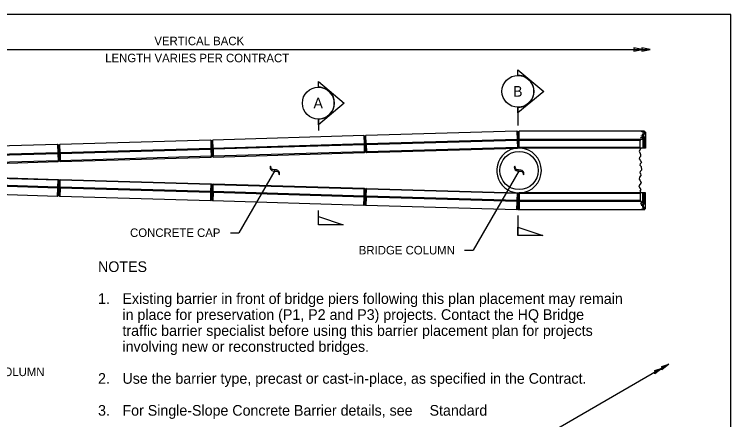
# Model space of a CAD drawing. Extents: x 99862 to 103151, y 100000 to 102076.
# Drawn here: x 101804 to 103151, y 101314 to 102076 of the extents above; entities that cross this region are included whole.
import ezdxf

# ---------------------------------------------------------------- set-up
doc = ezdxf.new("R2010")
doc.units = 0
for name, color, linetype in [('Level 1', 7, 'Continuous'), ('Level 15', 7, 'Continuous'), ('Level 19', 7, 'Continuous'), ('Level 2', 7, 'Continuous'), ('Level 20', 7, 'Continuous'), ('Level 25', 7, 'Continuous'), ('Level 41', 7, 'Continuous'), ('Level 60', 7, 'Continuous'), ('Level 8', 7, 'Continuous'), ('Level 9', 7, 'Continuous')]:
    doc.layers.add(name, color=color, linetype=linetype)

msp = doc.modelspace()

# ---------------------------------------------------------------- linework, layer by layer
at = {"layer": 'Level 1'}
msp.add_lwpolyline([(99862, 99999.5), (103151, 99999.5), (103151, 102075.5), (99862, 102075.5)], close=True, dxfattribs=at)
at = {"layer": 'Level 15'}
for p, q in [((101310.7, 102009.5), (102999.7, 102009.5)), ((102293.6, 101782.2), (102226.1, 101665.2)), ((102753, 101782.1), (102666.6, 101632.4)), ((102210.1, 101665.2), (102226.1, 101665.2)), ((102650.6, 101632.4), (102666.6, 101632.4)), ((103034.9, 101418.4), (101857.3, 100738.4))]:
    msp.add_line(p, q, dxfattribs=at)
for points in [[(102984.7, 102009.5), (102969, 102012.6), (102969.7, 102009.5), (102969, 102006.4)], [(102999.7, 102009.5), (102984, 102012.6), (102984.7, 102009.5), (102984, 102006.4)]]:
    msp.add_lwpolyline(points, close=True, dxfattribs=at)
at = {"layer": 'Level 19'}
for p, q in [((102754.9, 101824.1), (102751.1, 101824.1)), ((102751.1, 101740.2), (102754.9, 101740.2))]:
    msp.add_line(p, q, dxfattribs=at)
msp.add_circle((102753, 101782.1), 36, dxfattribs=at)
for start, end in [(92.5929, 240), (272.5929, 87.4071), (240, 267.4071)]:
    msp.add_arc((102753, 101782.1), 42, start, end, dxfattribs=at)
at = {"layer": 'Level 2'}
for p, q in [((102748.9, 101856.1), (102465, 101847.8)), ((102748.9, 101856.1), (102749.3, 101840.3)), ((102750.4, 101854.6), (102748.9, 101856.1)), ((102750.4, 101854.6), (102750.9, 101838.9)), ((102750.4, 101854.6), (102751.4, 101854.6)), ((102751.4, 101854.6), (102752.9, 101856.1)), ((102751.4, 101838.9), (102751.4, 101854.6)), ((102752.9, 101840.4), (102752.9, 101856.1)), ((102988.8, 101856.1), (102752.9, 101856.1)), ((102982.8, 101855.3), (102988.8, 101856.1)), ((102990.8, 101854.3), (102982.8, 101855.3)), ((102984.9, 101852.8), (102988.1, 101853.5)), ((102988.1, 101853.5), (102990.8, 101854.3)), ((102988.1, 101853.5), (102988.1, 101851.9)), ((102988.8, 101856.1), (102988.8, 101854.6)), ((102990.8, 101854.3), (102990.8, 101851.2)), ((102461, 101847.7), (102177.1, 101839.4)), ((102462.5, 101846.2), (102461, 101847.7)), ((102461, 101847.7), (102461.5, 101832)), ((102463.5, 101846.2), (102462.5, 101846.2)), ((102463, 101830.5), (102462.5, 101846.2)), ((102463.5, 101846.2), (102465, 101847.8)), ((102464, 101830.5), (102463.5, 101846.2)), ((102465.5, 101832.1), (102465, 101847.8)), ((102749.3, 101840.3), (102465.5, 101832.1)), ((102749.3, 101840.3), (102750.1, 101839.5)), ((102750.1, 101839.5), (102749.4, 101838.6)), ((102750.1, 101839.5), (102750.9, 101838.9)), ((102752.2, 101839.5), (102751.4, 101838.9)), ((102752.9, 101840.4), (102752.2, 101839.5)), ((102752.2, 101839.5), (102752.9, 101838.6)), ((102982, 101840.4), (102752.9, 101840.4)), ((102980.5, 101838.6), (102982, 101840.4)), ((102981.7, 101844), (102987, 101845.1)), ((102982.8, 101842.9), (102981.7, 101844)), ((102982, 101840.4), (102986, 101841.1)), ((102982.8, 101847.5), (102987, 101848.2)), ((102983.3, 101846.8), (102982.8, 101847.5)), ((102986, 101842.1), (102982.8, 101842.9)), ((102988.6, 101845.7), (102983.3, 101846.8)), ((102984.4, 101849.6), (102987, 101850.4)), ((102987, 101848.2), (102984.4, 101849.6)), ((102990.8, 101851.2), (102984.9, 101852.8)), ((102986, 101841.1), (102986, 101842.1)), ((102986, 101841.1), (102986, 101824.1)), ((102987, 101850.4), (102990.8, 101851.2)), ((102987, 101850.4), (102987, 101848.2)), ((102987, 101848.2), (102987, 101846)), ((102987, 101845.1), (102988.6, 101845.7)), ((102987, 101845.1), (102987, 101824.1)), ((102988.6, 101845.7), (102988.6, 101824.1)), ((102990.8, 101851.2), (102990.8, 101824.1)), ((101885.2, 101830.9), (101601.4, 101822.6)), ((101886.8, 101829.4), (101885.2, 101830.9)), ((101885.2, 101830.9), (101885.7, 101815.2)), ((101887.8, 101829.4), (101886.8, 101829.4)), ((101887.2, 101813.7), (101886.8, 101829.4)), ((101887.8, 101829.4), (101889.2, 101831)), ((101888.2, 101813.7), (101887.8, 101829.4)), ((102173.1, 101839.3), (101889.2, 101831)), ((101889.7, 101815.3), (101889.2, 101831)), ((102174.7, 101837.8), (102173.1, 101839.3)), ((102173.1, 101839.3), (102173.6, 101823.6)), ((102175.7, 101837.8), (102174.7, 101837.8)), ((102175.1, 101822.1), (102174.7, 101837.8)), ((102175.7, 101837.8), (102177.1, 101839.4)), ((102176.1, 101822.1), (102175.7, 101837.8)), ((102177.6, 101823.7), (102177.1, 101839.4)), ((102461.5, 101832), (102177.6, 101823.7)), ((102461.5, 101830.2), (102177.6, 101821.9)), ((102461.5, 101832), (102462.2, 101831.1)), ((102462.2, 101831.1), (102461.5, 101830.2)), ((102461.5, 101830.2), (102461.9, 101817.2)), ((102462.2, 101831.1), (102463, 101830.5)), ((102464, 101830.5), (102463, 101830.5)), ((102463.4, 101817.2), (102463, 101830.5)), ((102464.7, 101831.2), (102464, 101830.5)), ((102464.4, 101817.3), (102464, 101830.5)), ((102465.5, 101832.1), (102464.7, 101831.2)), ((102464.7, 101831.2), (102465.5, 101830.3)), ((102749.4, 101838.6), (102465.5, 101830.3)), ((102465.5, 101830.3), (102465.9, 101817.3)), ((102749.4, 101838.6), (102749.8, 101825.6)), ((102751.3, 101825.6), (102750.9, 101838.9)), ((102751.4, 101825.6), (102751.4, 101838.9)), ((102752.9, 101825.6), (102752.9, 101838.6)), ((102980.5, 101838.6), (102752.9, 101838.6)), ((102980.5, 101825.6), (102980.5, 101838.6)), ((101885.7, 101815.2), (101601.8, 101806.9)), ((101885.7, 101813.4), (101601.9, 101805.1)), ((101885.7, 101815.2), (101886.5, 101814.3)), ((101886.5, 101814.3), (101885.7, 101813.4)), ((101885.7, 101813.4), (101886.1, 101800.4)), ((101886.5, 101814.3), (101887.2, 101813.7)), ((101888.2, 101813.7), (101887.2, 101813.7)), ((101887.6, 101800.4), (101887.2, 101813.7)), ((101889, 101814.4), (101888.2, 101813.7)), ((101888.6, 101800.5), (101888.2, 101813.7)), ((101889.7, 101815.3), (101889, 101814.4)), ((101889, 101814.4), (101889.7, 101813.5)), ((102173.6, 101823.6), (101889.7, 101815.3)), ((102173.6, 101821.8), (101889.7, 101813.5)), ((101889.7, 101813.5), (101890.1, 101800.5)), ((102173.6, 101823.6), (102174.3, 101822.7)), ((102174.3, 101822.7), (102173.6, 101821.8)), ((102173.6, 101821.8), (102174, 101808.8)), ((102174.3, 101822.7), (102175.1, 101822.1)), ((102176.1, 101822.1), (102175.1, 101822.1)), ((102175.5, 101808.8), (102175.1, 101822.1)), ((102176.9, 101822.8), (102176.1, 101822.1)), ((102176.5, 101808.9), (102176.1, 101822.1)), ((102177.6, 101823.7), (102176.9, 101822.8)), ((102176.9, 101822.8), (102177.6, 101821.9)), ((102177.6, 101821.9), (102178, 101808.9)), ((102461.9, 101817.2), (102178, 101808.9)), ((102178, 101807.4), (102461.9, 101815.7)), ((102461.9, 101815.7), (102463.4, 101817.2)), ((102462.7, 101816.5), (102461.9, 101817.2)), ((102462.7, 101816.5), (102461.9, 101815.7)), ((102463.4, 101817.2), (102462.7, 101816.5)), ((102463.4, 101817.2), (102464.4, 101817.3)), ((102464.4, 101817.3), (102465.9, 101815.8)), ((102464.4, 101817.3), (102465.2, 101816.5)), ((102465.2, 101816.5), (102465.9, 101817.3)), ((102465.9, 101815.8), (102465.2, 101816.5)), ((102749.8, 101825.6), (102465.9, 101817.3)), ((102465.9, 101815.8), (102749.8, 101824.1)), ((102750.5, 101824.8), (102749.8, 101825.6)), ((102750.5, 101824.8), (102749.8, 101824.1)), ((102751.3, 101825.6), (102750.5, 101824.8)), ((102752.9, 101824.1), (102751.4, 101825.6)), ((102752.2, 101824.9), (102752.9, 101825.6)), ((102980.5, 101825.6), (102752.9, 101825.6)), ((102990.8, 101824.1), (102752.9, 101824.1)), ((102982, 101824.1), (102980.5, 101825.6)), ((101886.1, 101800.4), (101602.2, 101792.1)), ((101886.9, 101799.7), (101886.1, 101800.4)), ((101886.2, 101798.9), (101887.6, 101800.4)), ((101886.9, 101799.7), (101886.2, 101798.9)), ((101887.6, 101800.4), (101886.9, 101799.7)), ((101887.6, 101800.4), (101888.6, 101800.5)), ((101888.6, 101800.5), (101890.2, 101799)), ((101888.6, 101800.5), (101889.4, 101799.7)), ((101889.4, 101799.7), (101890.1, 101800.5)), ((101890.2, 101799), (101889.4, 101799.7)), ((102174, 101808.8), (101890.1, 101800.5)), ((101890.2, 101799), (102174, 101807.3)), ((102174, 101807.3), (102175.5, 101808.8)), ((102174.8, 101808.1), (102174, 101808.8)), ((102174.8, 101808.1), (102174, 101807.3)), ((102175.5, 101808.8), (102174.8, 101808.1)), ((102175.5, 101808.8), (102176.5, 101808.9)), ((102176.5, 101808.9), (102178, 101807.4)), ((102176.5, 101808.9), (102177.3, 101808.1)), ((102177.3, 101808.1), (102178, 101808.9)), ((102178, 101807.4), (102177.3, 101808.1)), ((101602.3, 101790.6), (101886.2, 101798.9)), ((101886.1, 101763.9), (101602.2, 101772.2)), ((101602.3, 101773.7), (101886.2, 101765.4)), ((101885.7, 101750.9), (101601.9, 101759.2)), ((101885.7, 101750.9), (101886.1, 101763.9)), ((101886.9, 101764.6), (101886.1, 101763.9)), ((101887.6, 101763.9), (101886.2, 101765.4)), ((101886.9, 101764.6), (101886.2, 101765.4)), ((101887.6, 101763.9), (101886.9, 101764.6)), ((101887.6, 101763.9), (101887.2, 101750.6)), ((101887.6, 101763.9), (101888.6, 101763.8)), ((101888.6, 101763.8), (101888.2, 101750.6)), ((101890.2, 101765.3), (101888.6, 101763.8)), ((101888.6, 101763.8), (101889.4, 101764.6)), ((101890.2, 101765.3), (101889.4, 101764.6)), ((101889.4, 101764.6), (101890.1, 101763.8)), ((101889.7, 101750.8), (101890.1, 101763.8)), ((102174, 101755.5), (101890.1, 101763.8)), ((101890.2, 101765.3), (102174, 101757)), ((101885.7, 101749.1), (101601.8, 101757.4)), ((101885.2, 101733.4), (101885.7, 101749.1)), ((101886.5, 101750), (101885.7, 101750.9)), ((101885.7, 101749.1), (101886.5, 101750)), ((101886.5, 101750), (101887.2, 101750.6)), ((101887.2, 101750.6), (101886.8, 101734.9)), ((101888.2, 101750.6), (101887.2, 101750.6)), ((101888.2, 101750.6), (101887.8, 101734.9)), ((101889, 101749.9), (101888.2, 101750.6)), ((101889, 101749.9), (101889.7, 101750.8)), ((101889.7, 101749), (101889, 101749.9)), ((101889.7, 101749), (101889.2, 101733.3)), ((102173.6, 101742.5), (101889.7, 101750.8)), ((102173.6, 101740.7), (101889.7, 101749)), ((102173.6, 101742.5), (102174, 101755.5)), ((102175.5, 101755.5), (102174, 101757)), ((102174.8, 101756.2), (102174, 101757)), ((102174.8, 101756.2), (102174, 101755.5)), ((102175.5, 101755.5), (102174.8, 101756.2)), ((102175.5, 101755.5), (102175.1, 101742.2)), ((102175.5, 101755.5), (102176.5, 101755.4)), ((102176.5, 101755.4), (102176.1, 101742.2)), ((102178, 101756.9), (102176.5, 101755.4)), ((102176.5, 101755.4), (102177.3, 101756.2)), ((102178, 101756.9), (102177.3, 101756.2)), ((102177.3, 101756.2), (102178, 101755.4)), ((102177.6, 101742.4), (102178, 101755.4)), ((102178, 101756.9), (102461.9, 101748.6)), ((102461.9, 101747.1), (102178, 101755.4)), ((102461.5, 101734.1), (102461.9, 101747.1)), ((102463.4, 101747.1), (102461.9, 101748.6)), ((102462.7, 101747.8), (102461.9, 101748.6)), ((102462.7, 101747.8), (102461.9, 101747.1)), ((102463.4, 101747.1), (102462.7, 101747.8)), ((102463.4, 101747.1), (102463, 101733.8)), ((102463.4, 101747.1), (102464.4, 101747)), ((102464.4, 101747), (102464, 101733.8)), ((102465.9, 101748.5), (102464.4, 101747)), ((102464.4, 101747), (102465.2, 101747.8)), ((102465.9, 101748.5), (102465.2, 101747.8)), ((102465.2, 101747.8), (102465.9, 101747)), ((102465.5, 101734), (102465.9, 101747)), ((102465.9, 101748.5), (102749.8, 101740.2)), ((102749.8, 101738.7), (102465.9, 101747)), ((101885.2, 101733.4), (101601.4, 101741.7)), ((101886.8, 101734.9), (101885.2, 101733.4)), ((101887.8, 101734.9), (101886.8, 101734.9)), ((101887.8, 101734.9), (101889.2, 101733.3)), ((102173.1, 101725), (101889.2, 101733.3)), ((102173.1, 101725), (102173.6, 101740.7)), ((102174.3, 101741.6), (102173.6, 101742.5)), ((102173.6, 101740.7), (102174.3, 101741.6)), ((102174.3, 101741.6), (102175.1, 101742.2)), ((102175.1, 101742.2), (102174.7, 101726.5)), ((102176.1, 101742.2), (102175.1, 101742.2)), ((102176.1, 101742.2), (102175.7, 101726.5)), ((102176.9, 101741.5), (102176.1, 101742.2)), ((102176.9, 101741.5), (102177.6, 101742.4)), ((102177.6, 101740.6), (102176.9, 101741.5)), ((102177.6, 101740.6), (102177.1, 101724.9)), ((102461.5, 101734.1), (102177.6, 101742.4)), ((102461.5, 101732.3), (102177.6, 101740.6)), ((102461, 101716.6), (102461.5, 101732.3)), ((102462.2, 101733.2), (102461.5, 101734.1)), ((102461.5, 101732.3), (102462.2, 101733.2)), ((102462.2, 101733.2), (102463, 101733.8)), ((102463, 101733.8), (102462.5, 101718.1)), ((102464, 101733.8), (102463, 101733.8)), ((102464, 101733.8), (102463.5, 101718.1)), ((102464.7, 101733.1), (102464, 101733.8)), ((102464.7, 101733.1), (102465.5, 101734)), ((102465.5, 101732.2), (102464.7, 101733.1)), ((102465.5, 101732.2), (102465, 101716.5)), ((102749.4, 101725.7), (102465.5, 101734)), ((102749.3, 101723.9), (102465.5, 101732.2)), ((102749.4, 101725.7), (102749.8, 101738.7)), ((102750.5, 101739.5), (102749.8, 101740.2)), ((102749.8, 101740.2), (102751.2, 101738.7)), ((102750.5, 101739.5), (102749.8, 101738.7)), ((102751.3, 101738.7), (102750.5, 101739.5)), ((102751.3, 101738.7), (102750.9, 101725.4)), ((102751.4, 101738.7), (102752.9, 101740.2)), ((102751.4, 101738.7), (102752.2, 101739.4)), ((102751.4, 101738.7), (102751.4, 101725.4)), ((102752.9, 101740.2), (102752.2, 101739.4)), ((102752.2, 101739.4), (102752.9, 101738.7)), ((102990.8, 101740.2), (102752.9, 101740.2)), ((102752.9, 101738.7), (102752.9, 101725.7)), ((102980.5, 101738.7), (102752.9, 101738.7)), ((102982, 101740.2), (102980.5, 101738.7)), ((102980.5, 101738.7), (102980.5, 101725.7)), ((102986, 101723.2), (102986, 101740.2)), ((102987, 101719.2), (102987, 101740.2)), ((102988.6, 101718.6), (102988.6, 101740.2)), ((102990.8, 101713.1), (102990.8, 101740.2)), ((102174.7, 101726.5), (102173.1, 101725)), ((102175.7, 101726.5), (102174.7, 101726.5)), ((102175.7, 101726.5), (102177.1, 101724.9)), ((102461, 101716.6), (102177.1, 101724.9)), ((102748.9, 101708.2), (102749.3, 101723.9)), ((102749.3, 101723.9), (102750.1, 101724.8)), ((102750.1, 101724.8), (102749.4, 101725.7)), ((102750.1, 101724.8), (102750.9, 101725.4)), ((102750.4, 101709.7), (102750.9, 101725.4)), ((102751.4, 101725.4), (102751.4, 101709.7)), ((102752.2, 101724.8), (102751.4, 101725.4)), ((102752.2, 101724.8), (102752.9, 101725.7)), ((102752.9, 101723.9), (102752.2, 101724.8)), ((102980.5, 101725.7), (102752.9, 101725.7)), ((102752.9, 101723.9), (102752.9, 101708.2)), ((102982, 101723.9), (102752.9, 101723.9)), ((102980.5, 101725.7), (102982, 101723.9)), ((102982.8, 101721.4), (102981.7, 101720.3)), ((102981.7, 101720.3), (102987, 101719.2)), ((102982, 101723.9), (102986, 101723.2)), ((102986, 101722.2), (102982.8, 101721.4)), ((102988.6, 101718.6), (102983.3, 101717.5)), ((102986, 101723.2), (102986, 101722.2)), ((102987, 101719.2), (102988.6, 101718.6)), ((102987, 101716.1), (102987, 101718.3)), ((102462.5, 101718.1), (102461, 101716.6)), ((102463.5, 101718.1), (102462.5, 101718.1)), ((102463.5, 101718.1), (102465, 101716.5)), ((102748.9, 101708.2), (102465, 101716.5)), ((102750.4, 101709.7), (102748.9, 101708.2)), ((102750.4, 101709.7), (102751.4, 101709.7)), ((102751.4, 101709.7), (102752.9, 101708.2)), ((102988.8, 101708.2), (102752.9, 101708.2)), ((102983.3, 101717.5), (102982.8, 101716.8)), ((102982.8, 101716.8), (102987, 101716.1)), ((102990.8, 101710), (102982.8, 101709)), ((102982.8, 101709), (102988.8, 101708.2)), ((102987, 101716.1), (102984.4, 101714.7)), ((102984.4, 101714.7), (102987, 101713.9)), ((102990.8, 101713.1), (102984.9, 101711.5)), ((102984.9, 101711.5), (102988.1, 101710.8)), ((102987, 101713.9), (102987, 101716.1)), ((102987, 101713.9), (102990.8, 101713.1)), ((102988.1, 101710.8), (102988.1, 101712.4)), ((102988.1, 101710.8), (102990.8, 101710)), ((102988.8, 101708.2), (102988.8, 101709.7)), ((102990.8, 101710), (102990.8, 101713.1))]:
    msp.add_line(p, q, dxfattribs=at)
at = {"layer": 'Level 20'}
for p, q in [((102285.7, 101790.1), (102284.6, 101788.2)), ((102284.6, 101788.2), (102285, 101786.1)), ((102285, 101786.1), (102285.6, 101784.5)), ((102286.7, 101786.5), (102285.7, 101790.1)), ((102287.5, 101785.1), (102286.7, 101786.5)), ((102745.1, 101790), (102744, 101788.2)), ((102744, 101788.2), (102744.4, 101786.1)), ((102744.4, 101786.1), (102745, 101784.4)), ((102746.1, 101786.5), (102745.1, 101790)), ((102747, 101785.1), (102746.1, 101786.5)), ((102285.6, 101784.5), (102286.6, 101783.2)), ((102286.6, 101783.2), (102287.9, 101782.2)), ((102288.6, 101784.2), (102287.5, 101785.1)), ((102287.9, 101782.2), (102290.2, 101781.3)), ((102290, 101783.7), (102288.6, 101784.2)), ((102292.5, 101783.5), (102290, 101783.7)), ((102290.2, 101781.3), (102294.3, 101781)), ((102296.8, 101783.1), (102292.5, 101783.5)), ((102294.3, 101781), (102296.8, 101780.8)), ((102299.4, 101782.2), (102296.8, 101783.1)), ((102296.8, 101780.8), (102298.7, 101780.2)), ((102298.7, 101780.2), (102299.7, 101779.3)), ((102300.8, 101781.1), (102299.4, 101782.2)), ((102299.7, 101779.3), (102300.5, 101778.2)), ((102300.5, 101778.2), (102301.1, 101776.6)), ((102301.8, 101779.7), (102300.8, 101781.1)), ((102301.1, 101776.6), (102301.7, 101774.2)), ((102301.7, 101774.2), (102302.7, 101776.1)), ((102302.5, 101778), (102301.8, 101779.7)), ((102302.7, 101776.1), (102302.5, 101778)), ((102745, 101784.4), (102746, 101783.1)), ((102746, 101783.1), (102747.3, 101782.1)), ((102748, 101784.2), (102747, 101785.1)), ((102747.3, 101782.1), (102749.6, 101781.2)), ((102749.4, 101783.6), (102748, 101784.2)), ((102751.9, 101783.4), (102749.4, 101783.6)), ((102749.6, 101781.2), (102753.7, 101781)), ((102756.2, 101783), (102751.9, 101783.4)), ((102753.7, 101781), (102756.2, 101780.7)), ((102756.2, 101780.7), (102758.1, 101780.1)), ((102758.8, 101782.1), (102756.2, 101783)), ((102758.1, 101780.1), (102759.1, 101779.3)), ((102760.2, 101781), (102758.8, 101782.1)), ((102759.1, 101779.3), (102759.9, 101778.2)), ((102759.9, 101778.2), (102760.5, 101776.6)), ((102761.2, 101779.7), (102760.2, 101781)), ((102760.5, 101776.6), (102761.1, 101774.2)), ((102761.1, 101774.2), (102762.1, 101776)), ((102761.9, 101778), (102761.2, 101779.7)), ((102762.1, 101776), (102761.9, 101778))]:
    msp.add_line(p, q, dxfattribs=at)
at = {"layer": 'Level 25'}
for points in [[(102465.9, 101817.3), (102461.9, 101817.2)], [(101890.1, 101800.5), (101886.1, 101800.4)], [(102178, 101808.9), (102174, 101808.8)], [(101886.1, 101763.9), (101890.1, 101763.8)], [(102174, 101755.5), (102178, 101755.4)], [(102461.9, 101747.1), (102465.9, 101747)]]:
    msp.add_lwpolyline(points, dxfattribs=at)
at = {"layer": 'Level 41'}
for p, q in [((102754.9, 101824.1), (102751.1, 101824.1)), ((102751.1, 101740.2), (102754.9, 101740.2))]:
    msp.add_line(p, q, dxfattribs=at)
msp.add_lwpolyline([(102982, 101824.1), (102978.6, 101818.6), (102980.6, 101814.2), (102981.3, 101811.9), (102981.3, 101808.5), (102979.3, 101806.5), (102979, 101803.9), (102981, 101801.2), (102983, 101797.2), (102980.6, 101794.5), (102980, 101792.2), (102982.7, 101789.8), (102983.3, 101782.5), (102980.6, 101780.1), (102980.3, 101777.8), (102981.3, 101776.5), (102982.3, 101772.5), (102979.3, 101769.8), (102979, 101765.8), (102980.3, 101763.8), (102982.7, 101759.8), (102980.6, 101756.4), (102978.3, 101753.1), (102980, 101749.1), (102982, 101746.4), (102980, 101743.4), (102982, 101740.2)], dxfattribs=at)
msp.add_circle((102753, 101782.1), 36, dxfattribs=at)
for start, end in [(92.5929, 240), (272.5929, 87.4071), (240, 267.4071)]:
    msp.add_arc((102753, 101782.1), 42, start, end, dxfattribs=at)
at = {"layer": 'Level 60'}
msp.add_line((103151, 102075.5), (103151, 102075.5), dxfattribs=at)
msp.add_line((103151, 102075.5), (103151, 102075.5), dxfattribs=at)
at = {"layer": 'Level 8'}
for points in [[(103022, 101410.9), (103008.3, 101400), (103009, 101403.4), (103008.3, 101406.1)], [(103034.9, 101418.4), (103021.3, 101407.5), (103022, 101410.9), (103021.3, 101413.6)]]:
    msp.add_lwpolyline(points, close=True, dxfattribs=at)
at = {"layer": 'Level 9'}
for p, q in [((102750.9, 101960.8), (102750.9, 101971.4)), ((102750.9, 101971.4), (102799.4, 101930.8)), ((102375.5, 101938.7), (102375.5, 101949.3)), ((102375.5, 101949.3), (102424, 101908.7)), ((102799.4, 101930.8), (102750.9, 101890.2)), ((102424, 101908.7), (102375.5, 101868.1)), ((102750.9, 101890.2), (102750.9, 101900.8)), ((102750.9, 101900.8), (102750.9, 101866.6)), ((102375.5, 101868.1), (102375.5, 101878.7)), ((102375.5, 101878.7), (102375.5, 101857.2)), ((102375.5, 101680.3), (102375.5, 101707.2)), ((102750.9, 101697.7), (102750.9, 101660.2))]:
    msp.add_line(p, q, dxfattribs=at)
for points in [[(102375.5, 101695.9), (102422.4, 101680.3), (102375.5, 101680.3)], [(102750.9, 101675.7), (102797.8, 101660.2), (102750.9, 101660.2)]]:
    msp.add_lwpolyline(points, close=True, dxfattribs=at)
for centre in [(102750.9, 101930.8), (102375.5, 101908.7)]:
    msp.add_circle(centre, 30, dxfattribs=at)
for centre in [(102750.9, 101930.8), (102375.5, 101908.7)]:
    msp.add_arc(centre, 30, 269.9978, 90.0022, dxfattribs=at)

# ---------------------------------------------------------------- texts
at = {"layer": 'Level 20'}
for s, height, p in [('VERTICAL BACK', 16, (102067.1, 102017.5)), ('LENGTH VARIES PER CONTRACT', 16, (101974.7, 101985.5)), ('B', 20, (102741.7, 101920.8)), ('A', 20, (102366.3, 101898.7)), ('CONCRETE CAP', 16, (102021.4, 101657.2)), ('BRIDGE COLUMN', 16, (102451.6, 101624.4)), ('NOTES', 20, (101961.2, 101591.4)), ('1.', 20, (101961.2, 101531.4)), ('Existing barrier in front of bridge piers following this plan placement may remain', 20, (102007.1, 101531.4)), ('in place for preservation (P1, P2 and P3) projects. Contact the HQ Bridge ', 20, (102007.1, 101501.4)), ('traffic barrier specialist before using this barrier placement plan for projects ', 20, (102007.1, 101471.4)), ('involving new or reconstructed bridges.', 20, (102007.1, 101441.4)), ('BRIDGE COLUMN', 16, (101679.8, 101395.8)), ('2.', 20, (101961.2, 101381.4)), ('Use the barrier type, precast or cast-in-place, as specified in the Contract.', 20, (102007.1, 101381.4)), ('3.', 20, (101961.2, 101321.4)), ('For Single-Slope Concrete Barrier details, see ', 20, (102007.1, 101321.4)), ('Standard', 20, (102584.7, 101321.4))]:
    msp.add_text(s, height=height, dxfattribs=at).set_placement(p)

doc.saveas('drawing.dxf')
